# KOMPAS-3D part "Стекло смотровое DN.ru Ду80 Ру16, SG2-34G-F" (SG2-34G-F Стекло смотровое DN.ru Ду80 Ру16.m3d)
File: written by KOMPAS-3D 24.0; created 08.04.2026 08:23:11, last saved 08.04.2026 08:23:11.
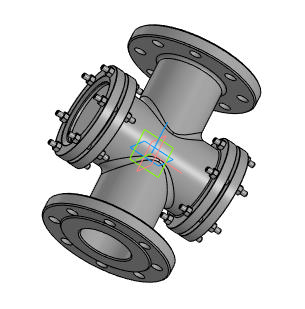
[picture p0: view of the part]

Document properties: Автор: Main; Полное имя файла: D:\DN.ru Аутсерс\Стекло смотровое DN.ru\SG2-34G-F Стекло смотровое DN.ru Ду80 Ру16\SG2-34G-F Стекло смотровое DN.ru Ду80 Ру16.m3d

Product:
- Part/product: Стекло смотровое DN.ru Ду80 Ру16  | designation SG2-34G-F
    Масса: 20.5
    Раздел спецификации: Прочие изделия
    Примечание: D500-00086

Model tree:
1. Операция без истории:1

Expressions: SG2-34G-F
